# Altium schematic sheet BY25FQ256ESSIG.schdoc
size 127 x 101 mm
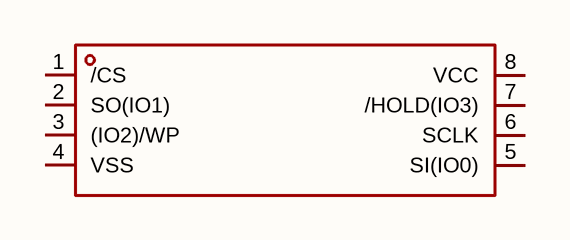
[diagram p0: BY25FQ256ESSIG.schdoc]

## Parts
U?  by25fq256essig  [SOP-8_L5.3-W5.3-P1.27-LS8.0-BL]  (value not drawn)

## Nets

Not connected (* = marked no-connect by the designer): U? 1(/CS) 2(SO(IO1)) 3((IO2)/WP) 4(VSS) 5(SI(IO0)) 6(SCLK) 7(/HOLD(IO3)) 8(VCC)

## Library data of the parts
U? = by25fq256essig: 接口类型:SPI;存储容量:256Mbit;时钟频率(fc):133MHz;; Manufacturer: BOYAMICRO(博雅); AddInBom: yes; ModelId: e456afcfff5840a795bdd4917416584f; ModelName: SOP-8_L5.2-W5.3-H2.1-LS7.9-P1.27; ModelTransform: 311.024,204.724,0,90,0,0,0,0.0005,0; Interface: SPI; Clock Frequency: 133MHz; Voltage - Supply: 2.7V~3.6V; Standby Supply Current: 1uA; Program / Erase Cycles: 100000次; Page Programming Time (Tpp): 300us; Data Retention - TDR (Year): 20年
